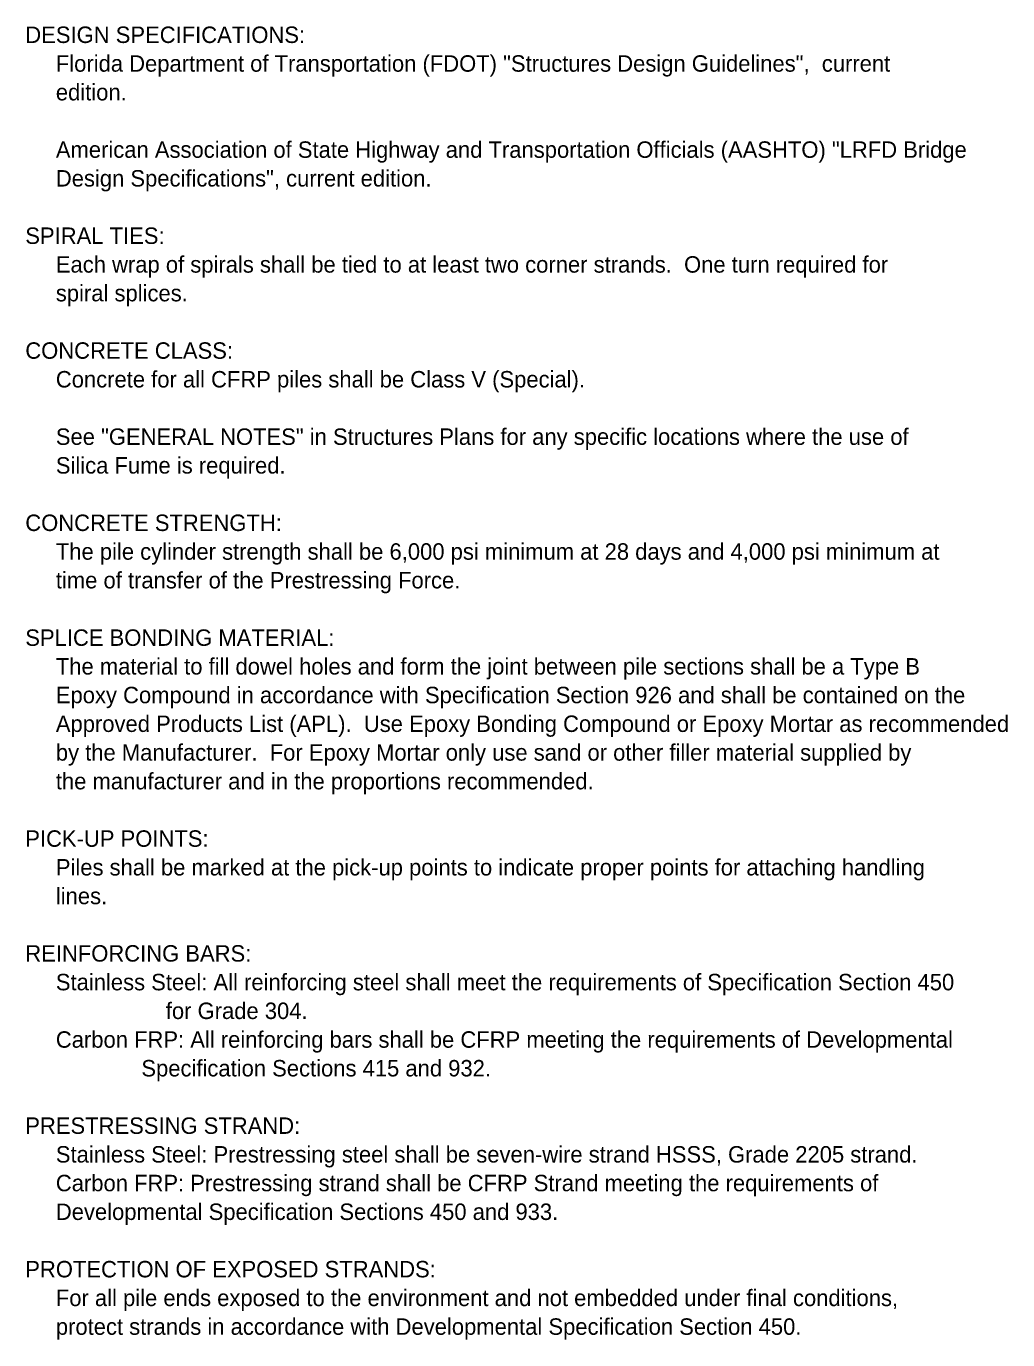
# Model space of a CAD drawing. Extents: x 120462 to 120592, y 120515 to 120635.
# Drawn here: x 120462.2 to 120474.23, y 120514.72 to 120530.82 of the extents above; entities that cross this region are included whole.
import ezdxf

# ---------------------------------------------------------------- set-up
doc = ezdxf.new("R2010")
doc.units = 0
doc.layers.add('AdhocPoint_dp', color=7, linetype='Continuous')

msp = doc.modelspace()

# ---------------------------------------------------------------- texts
at = {"layer": 'AdhocPoint_dp'}
for s, p in [('DESIGN SPECIFICATIONS:', (120462.187, 120530.617)), ('     Florida Department of Transportation (FDOT) "Structures Design Guidelines",  current', (120462.187, 120530.265)), ('     edition.', (120462.187, 120529.913)), ('     American Association of State Highway and Transportation Officials (AASHTO) "LRFD Bridge', (120462.187, 120529.209)), ('     Design Specifications", current edition.', (120462.187, 120528.857)), ('SPIRAL TIES:', (120462.187, 120528.153)), ('     Each wrap of spirals shall be tied to at least two corner strands.  One turn required for', (120462.187, 120527.801)), ('     spiral splices.', (120462.187, 120527.449)), ('CONCRETE CLASS:', (120462.187, 120526.745)), ('     Concrete for all CFRP piles shall be Class V (Special).', (120462.187, 120526.393)), ('     See "GENERAL NOTES" in Structures Plans for any specific locations where the use of ', (120462.187, 120525.689)), ('     Silica Fume is required.', (120462.187, 120525.337)), ('CONCRETE STRENGTH:', (120462.187, 120524.633)), ('     The pile cylinder strength shall be 6,000 psi minimum at 28 days and 4,000 psi minimum at', (120462.187, 120524.281)), ('     time of transfer of the Prestressing Force.', (120462.187, 120523.929)), ('SPLICE BONDING MATERIAL:', (120462.187, 120523.225)), ('     The material to fill dowel holes and form the joint between pile sections shall be a Type B', (120462.187, 120522.873)), ('     Epoxy Compound in accordance with Specification Section 926 and shall be contained on the', (120462.187, 120522.521)), ('     Approved Products List (APL).  Use Epoxy Bonding Compound or Epoxy Mortar as recommended', (120462.187, 120522.169)), ('     by the Manufacturer.  For Epoxy Mortar only use sand or other filler material supplied by', (120462.187, 120521.817)), ('     the manufacturer and in the proportions recommended. ', (120462.187, 120521.465)), ('PICK-UP POINTS:', (120462.187, 120520.761)), ('     Piles shall be marked at the pick-up points to indicate proper points for attaching handling', (120462.187, 120520.409)), ('     lines.', (120462.187, 120520.057)), ('REINFORCING BARS:', (120462.187, 120519.353)), ('     Stainless Steel: All reinforcing steel shall meet the requirements of Specification Section 450', (120462.187, 120519.001)), ('                       for Grade 304.', (120462.187, 120518.649)), ('     Carbon FRP: All reinforcing bars shall be CFRP meeting the requirements of Developmental', (120462.187, 120518.297)), ('                   Specification Sections 415 and 932.', (120462.187, 120517.945)), ('PRESTRESSING STRAND:', (120462.187, 120517.241)), ('     Stainless Steel: Prestressing steel shall be seven-wire strand HSSS, Grade 2205 strand.', (120462.187, 120516.889)), ('     Carbon FRP: Prestressing strand shall be CFRP Strand meeting the requirements of', (120462.187, 120516.537)), ('     Developmental Specification Sections 450 and 933.', (120462.187, 120516.185)), ('PROTECTION OF EXPOSED STRANDS:', (120462.187, 120515.481)), ('     For all pile ends exposed to the environment and not embedded under final conditions,', (120462.187, 120515.129)), ('     protect strands in accordance with Developmental Specification Section 450.', (120462.187, 120514.777))]:
    msp.add_text(s, height=0.2016, dxfattribs=at).set_placement(p)

doc.saveas('drawing.dxf')
